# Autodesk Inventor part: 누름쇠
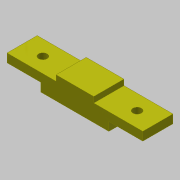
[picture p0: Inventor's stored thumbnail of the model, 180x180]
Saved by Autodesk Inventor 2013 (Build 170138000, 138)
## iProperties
Created: 2019-06
Part Number: 누름쇠
Material: 스테인리스강
Document SubType Name: Modeling
Designer: mduedu
Density: 1 g/cm^3
Author: mduedu
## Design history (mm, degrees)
sketch "스케치1"
  geometry: L1 (-36, 0)-(36, 0); L2 (36, 0)-(36, 12); L3 (36, 12)-(-36, 12); L4 (-36, 12)-(-36, 0); 2 further points
  constraints: 8 end point, 2 parallel, 1 coincident, 1 horizontal, 1 midpoint, 1 perpendicular
  dimensions: "d0" = 72 distance of L1.start L1.end; "d2" = 12 distance of L1.end L2.end
extrude "돌출1" new body sketch "스케치1" stored distance "d3" = 16; taper "d4" = 0 deg
sketch "스케치2"
  geometry: L1 (-36, 0)-(36, 0) reference; L2 (36, 0)-(36, 12) reference; L3 (36, 12)-(-36, 12) reference; L4 (-36, 12)-(-36, 0) reference; L5 (0, 0)-(0, 12); L6 (-36, 0)-(-18, 0); L7 (-18, 0)-(-18, 4.5); L8 (-18, 4.5)-(-36, 4.5); L9 (-36, 4.5)-(-36, 0); L10 (-36, 12)-(-10, 12); L11 (-10, 12)-(-10, 9); L12 (-10, 9)-(-36, 9); L13 (-36, 9)-(-36, 12); L14 (36, 12)-(36, 0); L15 (36, 0)-(18, 0); L16 (18, 0)-(18, 4.5); L17 (18, 4.5)-(36, 4.5); L18 (36, 4.5)-(36, 0); L19 (36, 12)-(10, 12); L20 (10, 12)-(10, 9); L21 (10, 9)-(36, 9); L22 (36, 9)-(36, 12)
  constraints: 36 end point, 6 symmetric about line, 4 parallel, 2 horizontal, 2 perpendicular, 1 midpoint
  dimensions: "d5" = 18 distance between parallel lines of L5 L7; "d7" = 4.5 distance between parallel lines of L1 L8; "d8" = 10 distance between parallel lines of L5 L11; "d9" = 3 distance between parallel lines of L12 L3
extrude "돌출2" cut sketch "스케치2" stored distance "d10" = 16; taper "d11" = 0 deg
sketch "스케치3"
  geometry: L1 (26, 0)-(26, 16) reference; L2 (0, 16)-(26, 16) reference; L3 (0, 0)-(0, 16) reference; L4 (26, 0)-(0, 0) reference; L5 (46, 0)-(26, 0) reference; L6 (46, 16)-(46, 0) reference; L7 (46, 16)-(72, 16) reference; L8 (72, 16)-(72, 0) reference; L9 (72, 0)-(46, 0) reference; L10 (26, 16)-(46, 16) reference; L11 (36, 16)-(36, 0); C1 r 2.25 at (11, 8); C2 r 2.25 at (61, 8); 1 further point
  constraints: 2 centre point, 2 end point, 2 midpoint, 1 horizontal alignment, 1 symmetric about line, 1 other
  dimensions: "d12" = 4.5 diameter of C1; "d13" = 25 distance of C1.centre point (36, 8)
extrude "돌출3" cut sketch "스케치3" stored distance "d14" = 16; taper "d15" = 0 deg
node "솔리드1"
node "투영된 루프1"
node "절단 모서리 투영1"
